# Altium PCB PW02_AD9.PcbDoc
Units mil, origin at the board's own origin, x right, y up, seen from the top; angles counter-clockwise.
Board outline 267.72 x 377.95 mil, 2 copper layers (Top, BOTTOM), stack 41.496 mil thick; 2 components, 0 nets, 12 pads, 0 vias.
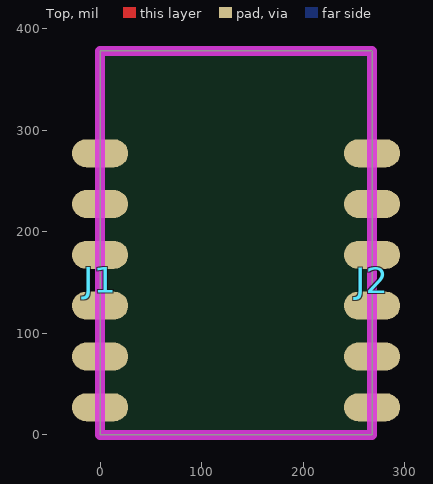
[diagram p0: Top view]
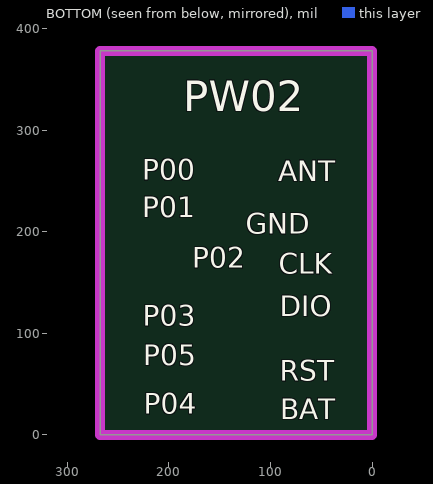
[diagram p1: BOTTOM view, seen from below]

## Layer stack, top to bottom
Top: signal copper 15.748
Dielectric: dielectric 10, FR-4, Dk 4.3
BOTTOM: signal copper 15.748

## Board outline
0,0 267.72,0 267.72,377.95 0,377.95

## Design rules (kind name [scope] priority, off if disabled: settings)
Clearance "'Default' PADS rule_18" [All] p1: gap=6
Clearance "'Default' PADS rule_15" [IsVia vs IsVia] p2: gap=6
ComponentClearance "'Default' PADS rule_12" [All] p1: gap=6 collisioncheckmode=3 verticalgap=10 showdistances=FALSE
FlightTimeFalling "'Default' PADS rule_10" [All] p1: maximum=10.00
FlightTimeRising "'Default' PADS rule_9" [All] p1: maximum=10.00
Length "'Default' PADS rule_5" [All] p1: maxlimit=50000 minlimit=0
MatchedLengths "'Default' PADS rule_11" [InNetClass('All Nets')] p1: tolerance=200 checknetsindiffpair=TRUE checkdiffpairvsdiffpair=TRUE checkothers=TRUE
MaxMinImpedance "'Default' PADS rule_8" [All] p1: minimum=50.00 maximum=150.0
ParallelSegment "'Default' PADS rule_7" [All] p1: limit=1000 gap=200
ParallelSegment "'Default' PADS rule_6" [All] p2: limit=1000 gap=200
PlaneClearance "'Default' PADS rule_14" [All] p1: clearance=6
PlaneConnect "Power Plane Connect Style - Via from round thru-hole global defaults" [IsVia] p1: planeconnectstyle=Direct reliefexpansion=20 reliefentries=4 reliefconductorwidth=15 reliefairgap=10
PlaneConnect "Power Plane Connect Style - Round thru-hole pad from global defaults" [IsPad And OnMultiLayer And (PadShape_MidLayer1 = 'Round') And (PadXSize_MidLayer1 = PadYSize_MidLayer1)] p2: planeconnectstyle=Direct reliefexpansion=20 reliefentries=4 reliefconductorwidth=15 reliefairgap=10
PlaneConnect "Power Plane Connect Style - Square thru-hole pad from global defaults" [IsPad And OnMultiLayer And ((PadShape_MidLayer1 = 'Rectangular') Or (PadShape_MidLayer1 = 'Octagonal') Or (PadShape_MidLayer1 = 'Rounded Rectangle')) And (PadXSize_MidLayer1 = PadYSize_MidLayer1)] p3: planeconnectstyle=Direct reliefexpansion=20 reliefentries=4 reliefconductorwidth=15 reliefairgap=10
PlaneConnect "Power Plane Connect Style - Rect thru-hole pad from global defaults" [IsPad And OnMultiLayer And ((PadShape_MidLayer1 = 'Rectangular') Or (PadShape_MidLayer1 = 'Octagonal') Or (PadShape_MidLayer1 = 'Rounded Rectangle')) And (PadXSize_MidLayer1 <> PadYSize_MidLayer1)] p4: planeconnectstyle=Direct reliefexpansion=20 reliefentries=4 reliefconductorwidth=15 reliefairgap=10
PlaneConnect "Power Plane Connect Style - Square-rect thru-hole pad from global defaults" [IsPad And OnMultiLayer And (PadShape_MidLayer1 = 'Rounded Rectangle') And (PadXSize_MidLayer1 = PadYSize_MidLayer1) And (Pad_CornerRadius_MidLayer1 = '0%')] p5: planeconnectstyle=Direct reliefexpansion=20 reliefentries=4 reliefconductorwidth=15 reliefairgap=10
PlaneConnect "Power Plane Connect Style - Oval thru-hole pad from global defaults" [IsPad And OnMultiLayer And (PadShape_MidLayer1 = 'Round') And (PadXSize_MidLayer1 <> PadYSize_MidLayer1)] p6: planeconnectstyle=Direct reliefexpansion=20 reliefentries=4 reliefconductorwidth=15 reliefairgap=10
PlaneConnect "Power Plane Connect Style - Round-oval thru-hole pad from global defaults" [IsPad And OnMultiLayer And (PadShape_MidLayer1 = 'Rounded Rectangle') And (PadXSize_MidLayer1 = PadYSize_MidLayer1) And (Pad_CornerRadius_MidLayer1 = '100%')] p7: planeconnectstyle=Direct reliefexpansion=20 reliefentries=4 reliefconductorwidth=15 reliefairgap=10
PolygonConnect "Polygon Connect Style - BOTTOM Round SMD from global defaults" [IsSMTPin And (PadShape_BottomLayer = 'Round') And (PadXSize_BottomLayer = PADYSize_BottomLayer) vs Layer = 'BOTTOM'] p1: connectstyle=Direct reliefconductorwidth=10 reliefentries=4 polygonreliefangle="45 Angle" airgapwidth=10
PolygonConnect "Polygon Connect Style - Top Round SMD from global defaults" [IsSMTPin And (PadShape_TopLayer = 'Round') And (PadXSize_TopLayer = PADYSize_TopLayer) vs Layer = 'Top'] p2: connectstyle=Direct reliefconductorwidth=10 reliefentries=4 polygonreliefangle="45 Angle" airgapwidth=10
PolygonConnect "Polygon Connect Style - BOTTOM Square SMD from global defaults 1" [IsSMTPin And (PadShape_BottomLayer = 'Rectangular') And (PadXSize_BottomLayer = PADYSize_BottomLayer) vs Layer = 'BOTTOM'] p3: connectstyle=Direct reliefconductorwidth=10 reliefentries=4 polygonreliefangle="45 Angle" airgapwidth=10
PolygonConnect "Polygon Connect Style - BOTTOM Square SMD from global defaults 2" [IsSMTPin And (PadShape_BottomLayer = 'Octagonal') And (PadXSize_BottomLayer = PADYSize_BottomLayer) vs Layer = 'BOTTOM'] p4: connectstyle=Direct reliefconductorwidth=10 reliefentries=4 polygonreliefangle="45 Angle" airgapwidth=10
PolygonConnect "Polygon Connect Style - BOTTOM Square SMD from global defaults 3" [IsSMTPin And (PadShape_BottomLayer = 'Rounded Rectangle') And (PadXSize_BottomLayer = PADYSize_BottomLayer) vs Layer = 'BOTTOM'] p5: connectstyle=Direct reliefconductorwidth=10 reliefentries=4 polygonreliefangle="45 Angle" airgapwidth=10
PolygonConnect "Polygon Connect Style - Top Square SMD from global defaults 1" [IsSMTPin And (PadShape_TopLayer = 'Rectangular') And (PadXSize_TopLayer = PADYSize_TopLayer) vs Layer = 'Top'] p6: connectstyle=Direct reliefconductorwidth=10 reliefentries=4 polygonreliefangle="45 Angle" airgapwidth=10
PolygonConnect "Polygon Connect Style - Top Square SMD from global defaults 2" [IsSMTPin And (PadShape_TopLayer = 'Octagonal') And (PadXSize_TopLayer = PADYSize_TopLayer) vs Layer = 'Top'] p7: connectstyle=Direct reliefconductorwidth=10 reliefentries=4 polygonreliefangle="45 Angle" airgapwidth=10
PolygonConnect "Polygon Connect Style - Top Square SMD from global defaults 3" [IsSMTPin And (PadShape_TopLayer = 'Rounded Rectangle') And (PadXSize_TopLayer = PADYSize_TopLayer) vs Layer = 'Top'] p8: connectstyle=Direct reliefconductorwidth=10 reliefentries=4 polygonreliefangle="45 Angle" airgapwidth=10
PolygonConnect "Polygon Connect Style - BOTTOM Rect SMD from global defaults 1" [IsSMTPin And (PadShape_BottomLayer = 'Rectangular') And (PadXSize_BottomLayer <> PADYSize_BottomLayer) vs Layer = 'BOTTOM'] p9: connectstyle=Direct reliefconductorwidth=10 reliefentries=4 polygonreliefangle="45 Angle" airgapwidth=10
PolygonConnect "Polygon Connect Style - BOTTOM Rect SMD from global defaults 2" [IsSMTPin And (PadShape_BottomLayer = 'Octagonal') And (PadXSize_BottomLayer <> PADYSize_BottomLayer) vs Layer = 'BOTTOM'] p10: connectstyle=Direct reliefconductorwidth=10 reliefentries=4 polygonreliefangle="45 Angle" airgapwidth=10
PolygonConnect "Polygon Connect Style - BOTTOM Rect SMD from global defaults 3" [IsSMTPin And (PadShape_BottomLayer = 'Rounded Rectangle') And (PadXSize_BottomLayer <> PADYSize_BottomLayer) vs Layer = 'BOTTOM'] p11: connectstyle=Direct reliefconductorwidth=10 reliefentries=4 polygonreliefangle="45 Angle" airgapwidth=10
PolygonConnect "Polygon Connect Style - BOTTOM Square-rect SMD pad from global defaults" [IsSMTPin And (PadShape_BottomLayer = 'Rounded Rectangle') And (PadXSize_BottomLayer = PADYSize_BottomLayer) And (Pad_CornerRadius_BottomLayer = '0%') vs Layer = 'BOTTOM'] p12: connectstyle=Direct reliefconductorwidth=10 reliefentries=4 polygonreliefangle="45 Angle" airgapwidth=10
PolygonConnect "Polygon Connect Style - Top Rect SMD from global defaults 1" [IsSMTPin And (PadShape_TopLayer = 'Rectangular') And (PadXSize_TopLayer <> PADYSize_TopLayer) vs Layer = 'Top'] p13: connectstyle=Direct reliefconductorwidth=10 reliefentries=4 polygonreliefangle="45 Angle" airgapwidth=10
PolygonConnect "Polygon Connect Style - Top Rect SMD from global defaults 2" [IsSMTPin And (PadShape_TopLayer = 'Octagonal') And (PadXSize_TopLayer <> PADYSize_TopLayer) vs Layer = 'Top'] p14: connectstyle=Direct reliefconductorwidth=10 reliefentries=4 polygonreliefangle="45 Angle" airgapwidth=10
PolygonConnect "Polygon Connect Style - Top Rect SMD from global defaults 3" [IsSMTPin And (PadShape_TopLayer = 'Rounded Rectangle') And (PadXSize_TopLayer <> PADYSize_TopLayer) vs Layer = 'Top'] p15: connectstyle=Direct reliefconductorwidth=10 reliefentries=4 polygonreliefangle="45 Angle" airgapwidth=10
PolygonConnect "Polygon Connect Style - Top Square-rect SMD pad from global defaults" [IsSMTPin And (PadShape_TopLayer = 'Rounded Rectangle') And (PadXSize_TopLayer = PADYSize_TopLayer) And (Pad_CornerRadius_TopLayer = '0%') vs Layer = 'Top'] p16: connectstyle=Direct reliefconductorwidth=10 reliefentries=4 polygonreliefangle="45 Angle" airgapwidth=10
PolygonConnect "Polygon Connect Style - BOTTOM Oval SMD from global defaults" [IsSMTPin And (PadShape_BottomLayer = 'Round') And (PadXSize_BottomLayer <> PADYSize_BottomLayer) vs Layer = 'BOTTOM'] p17: connectstyle=Direct reliefconductorwidth=10 reliefentries=4 polygonreliefangle="45 Angle" airgapwidth=10
PolygonConnect "Polygon Connect Style - BOTTOM Round-oval SMD pad from global defaults" [IsSMTPin And (PadShape_BottomLayer = 'Rounded Rectangle') And (PadXSize_BottomLayer = PADYSize_BottomLayer) And (Pad_CornerRadius_BottomLayer = '100%') vs Layer = 'BOTTOM'] p18: connectstyle=Direct reliefconductorwidth=10 reliefentries=4 polygonreliefangle="45 Angle" airgapwidth=10
PolygonConnect "Polygon Connect Style - Top Oval SMD from global defaults" [IsSMTPin And (PadShape_TopLayer = 'Round') And (PadXSize_TopLayer <> PADYSize_TopLayer) vs Layer = 'Top'] p19: connectstyle=Direct reliefconductorwidth=10 reliefentries=4 polygonreliefangle="45 Angle" airgapwidth=10
PolygonConnect "Polygon Connect Style - Top Round-oval SMD pad from global defaults" [IsSMTPin And (PadShape_TopLayer = 'Rounded Rectangle') And (PadXSize_TopLayer = PADYSize_TopLayer) And (Pad_CornerRadius_TopLayer = '100%') vs Layer = 'Top'] p20: connectstyle=Direct reliefconductorwidth=10 reliefentries=4 polygonreliefangle="45 Angle" airgapwidth=10
PolygonConnect "Polygon Connect Style - Via from round thru-hole global defaults_19" [IsVia] p21: connectstyle=Direct reliefconductorwidth=15 reliefentries=4 polygonreliefangle="45 Angle" airgapwidth=10
PolygonConnect "Polygon Connect Style - BOTTOM Round thru-hole pad from global defaults" [IsPad And OnMultiLayer And (PadShape_BottomLayer = 'Round') And (PadXSize_BottomLayer = PADYSize_BottomLayer) vs Layer = 'BOTTOM'] p22: connectstyle=Direct reliefconductorwidth=15 reliefentries=4 polygonreliefangle="45 Angle" airgapwidth=10
PolygonConnect "Polygon Connect Style - Via from round thru-hole global defaults" [IsVia] p23: connectstyle=Direct reliefconductorwidth=15 reliefentries=4 polygonreliefangle="45 Angle" airgapwidth=10
PolygonConnect "Polygon Connect Style - Top Round thru-hole pad from global defaults" [IsPad And OnMultiLayer And (PadShape_TopLayer = 'Round') And (PadXSize_TopLayer = PADYSize_TopLayer) vs Layer = 'Top'] p24: connectstyle=Direct reliefconductorwidth=15 reliefentries=4 polygonreliefangle="45 Angle" airgapwidth=10
PolygonConnect "Polygon Connect Style - BOTTOM Square thru-hole pad from global defaults" [IsPad And OnMultiLayer And ((PadShape_BottomLayer = 'Rectangular') Or (PadShape_BottomLayer = 'Octagonal') Or (PadShape_BottomLayer = 'Rounded Rectangle')) And (PadXSize_BottomLayer = PADYSize_BottomLayer) vs Layer = 'BOTTOM'] p25: connectstyle=Direct reliefconductorwidth=15 reliefentries=4 polygonreliefangle="45 Angle" airgapwidth=10
PolygonConnect "Polygon Connect Style - Top Square thru-hole pad from global defaults" [IsPad And OnMultiLayer And ((PadShape_TopLayer = 'Rectangular') Or (PadShape_TopLayer = 'Octagonal') Or (PadShape_TopLayer = 'Rounded Rectangle')) And (PadXSize_TopLayer = PADYSize_TopLayer) vs Layer = 'Top'] p26: connectstyle=Direct reliefconductorwidth=15 reliefentries=4 polygonreliefangle="45 Angle" airgapwidth=10
PolygonConnect "Polygon Connect Style - BOTTOM Rect thru-hole pad from global defaults" [IsPad And OnMultiLayer And ((PadShape_BottomLayer = 'Rectangular') Or (PadShape_BottomLayer = 'Octagonal') Or (PadShape_BottomLayer = 'Rounded Rectangle')) And (PadXSize_BottomLayer <> PADYSize_BottomLayer) vs Layer = 'BOTTOM'] p27: connectstyle=Direct reliefconductorwidth=15 reliefentries=4 polygonreliefangle="45 Angle" airgapwidth=10
PolygonConnect "Polygon Connect Style - BOTTOM Square-rect thru-hole pad from global defaults" [IsPad And OnMultiLayer And (PadShape_BottomLayer = 'Rounded Rectangle') And (PadXSize_BottomLayer = PADYSize_BottomLayer) And (Pad_CornerRadius_BottomLayer = '0%') vs Layer = 'BOTTOM'] p28: connectstyle=Direct reliefconductorwidth=15 reliefentries=4 polygonreliefangle="45 Angle" airgapwidth=10
PolygonConnect "Polygon Connect Style - Top Rect thru-hole pad from global defaults" [IsPad And OnMultiLayer And ((PadShape_TopLayer = 'Rectangular') Or (PadShape_TopLayer = 'Octagonal') Or (PadShape_TopLayer = 'Rounded Rectangle')) And (PadXSize_TopLayer <> PADYSize_TopLayer) vs Layer = 'Top'] p29: connectstyle=Direct reliefconductorwidth=15 reliefentries=4 polygonreliefangle="45 Angle" airgapwidth=10
PolygonConnect "Polygon Connect Style - Top Square-rect thru-hole pad from global defaults" [IsPad And OnMultiLayer And (PadShape_TopLayer = 'Rounded Rectangle') And (PadXSize_TopLayer = PADYSize_TopLayer) And (Pad_CornerRadius_TopLayer = '0%') vs Layer = 'Top'] p30: connectstyle=Direct reliefconductorwidth=15 reliefentries=4 polygonreliefangle="45 Angle" airgapwidth=10
PolygonConnect "Polygon Connect Style - BOTTOM Oval thru-hole pad from global defaults" [IsPad And OnMultiLayer And (PadShape_BottomLayer = 'Round') And (PadXSize_BottomLayer <> PADYSize_BottomLayer) vs Layer = 'BOTTOM'] p31: connectstyle=Direct reliefconductorwidth=15 reliefentries=4 polygonreliefangle="45 Angle" airgapwidth=10
PolygonConnect "Polygon Connect Style - BOTTOM Round-oval thru-hole pad from global defaults" [IsPad And OnMultiLayer And (PadShape_BottomLayer = 'Rounded Rectangle') And (PadXSize_BottomLayer = PADYSize_BottomLayer) And (Pad_CornerRadius_BottomLayer = '100%') vs Layer = 'BOTTOM'] p32: connectstyle=Direct reliefconductorwidth=15 reliefentries=4 polygonreliefangle="45 Angle" airgapwidth=10
PolygonConnect "Polygon Connect Style - Top Oval thru-hole pad from global defaults" [IsPad And OnMultiLayer And (PadShape_TopLayer = 'Round') And (PadXSize_TopLayer <> PADYSize_TopLayer) vs Layer = 'Top'] p33: connectstyle=Direct reliefconductorwidth=15 reliefentries=4 polygonreliefangle="45 Angle" airgapwidth=10
PolygonConnect "Polygon Connect Style - Top Round-oval thru-hole pad from global defaults" [IsPad And OnMultiLayer And (PadShape_TopLayer = 'Rounded Rectangle') And (PadXSize_TopLayer = PADYSize_TopLayer) And (Pad_CornerRadius_TopLayer = '100%') vs Layer = 'Top'] p34: connectstyle=Direct reliefconductorwidth=15 reliefentries=4 polygonreliefangle="45 Angle" airgapwidth=10
PolygonConnect [All] p35: connectstyle=Relief reliefconductorwidth=10 reliefentries=4 polygonreliefangle="90 Angle" airgapwidth=10
RoutingLayers "'Default' PADS rule_3" [All] p1: top layer_v5=TRUE bottom layer_v5=TRUE
RoutingPriority "'Default' PADS rule_2" [All] p1: routingpriority=3
RoutingTopology "'Default' PADS rule" [All] p1: topology=Shortest
RoutingVias "'Default' PADS rule_4" [All] p1: holewidth=7.87 width=13.78 viastyle="Through Hole" minholewidth=7.87 minwidth=13.78 maxholewidth=7.87 maxwidth=13.78
SMDToCorner "'Default' PADS rule_16" [All] p1: distance=60000
SMDToPlane "'Default' PADS rule_17" [All] p1: distance=60000
SolderMaskExpansion [All] p1: expansion=4
Width "'Default' PADS rule_13" [All] p1: maxlimit=60 minlimit=4 preferedwidth=5
22 further rules are at their usual default settings.

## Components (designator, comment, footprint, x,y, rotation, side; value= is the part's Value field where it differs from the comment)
J1 "CON6_1.27" CON6_1.27 0,177.17 r270 top
J2 "CON6_1.27" CON6_1.27 267.72,177.17 r270 top

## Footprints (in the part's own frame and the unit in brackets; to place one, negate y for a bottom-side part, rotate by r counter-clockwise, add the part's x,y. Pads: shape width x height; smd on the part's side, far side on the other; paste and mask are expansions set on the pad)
CON6_1.27 [mm]
  oval 0.7x1.4 smd: 1(-2.54,0) 2(-1.27,0) 3(0,0) 4(1.27,0) 5(2.54,0) 6(3.81,0)

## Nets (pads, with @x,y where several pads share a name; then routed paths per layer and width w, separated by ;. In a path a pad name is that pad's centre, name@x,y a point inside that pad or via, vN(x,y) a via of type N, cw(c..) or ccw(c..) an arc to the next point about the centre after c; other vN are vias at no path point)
pads on no net: J1.1 J1.2 J1.3 J1.4 J1.5 J1.6 J2.1 J2.2 J2.3 J2.4 J2.5 J2.6

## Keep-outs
Keep-Out Layer:
  the board outline again, w10

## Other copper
Top:
  pour cut-out: 43.47,295.49 43.47,378.7 240.11,378.7 240.11,295.49
BOTTOM:
  pour cut-out: 43.49,295.42 43.49,378.62 240.12,378.62 240.12,295.42

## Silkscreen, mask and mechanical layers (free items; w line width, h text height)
Silkscreen Bottom:
  text "PW02" at 185.81,318.33 h30
  text "P00" at 226.31,251.29 h20
  text "ANT" at 92.44,249.63 h20
  text "P01" at 226.13,214.04 h20
  text "GND" at 124.34,198.02 h20
  text "P02" at 177.25,164.71 h20
  text "CLK" at 92,158.34 h20
  text "DIO" at 90.69,116.85 h20
  text "P03" at 225.69,107.32 h20
  text "P05" at 225.31,68.34 h20
  text "RST" at 90.69,53.07 h20
  text "P04" at 224.9,20.74 h20
  text "BAT" at 90.25,15.41 h20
